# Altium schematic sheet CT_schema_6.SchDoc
size 278 x 170 mm
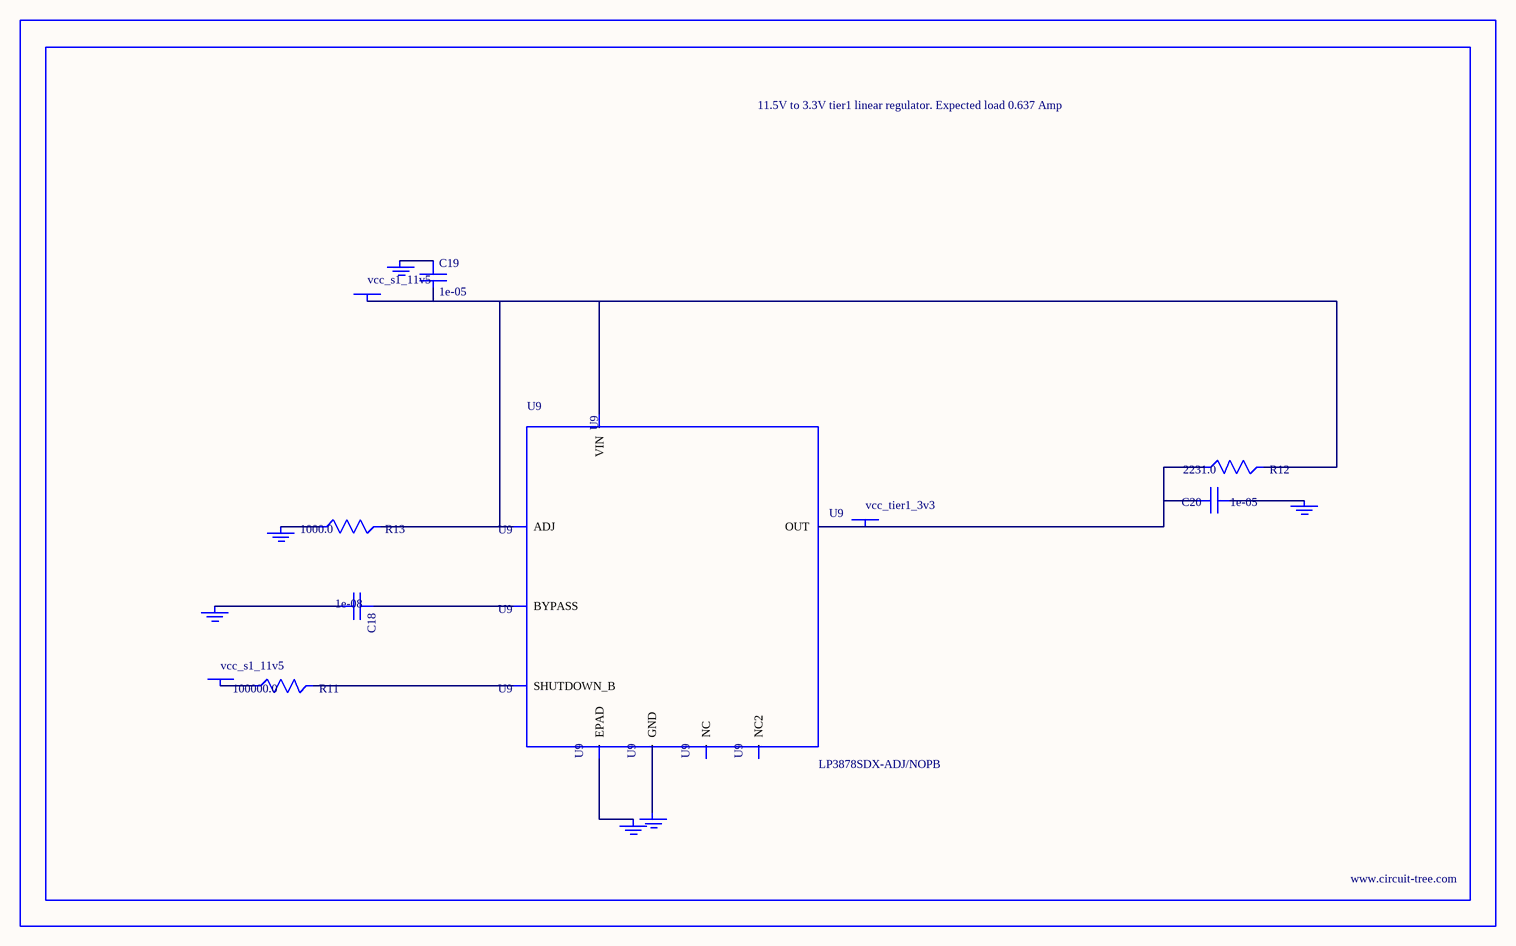
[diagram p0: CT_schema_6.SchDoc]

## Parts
BORDER5  (no value)
C18  1e-08  [C0402]
C19  1e-05  [C1210]
C20  1e-05  [C1210]
GND_INSTANCE_5_0  (no value)
GND_INSTANCE_5_1  (no value)
GND_INSTANCE_5_2  (no value)
GND_INSTANCE_5_3  (no value)
GND_INSTANCE_5_4  (no value)
GND_INSTANCE_5_5  (no value)
POWER_INSTANCE_5_0  vcc_s1_11v5
POWER_INSTANCE_5_1  vcc_s1_11v5
POWER_INSTANCE_5_2  vcc_tier1_3v3
R11  100000.0  [R0603]
R12  2231.0  [R0603]
R13  1000.0  [R0603]
U9  LP3878SDX-ADJ/NOPB  [WSON-8]

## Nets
NetC18_1: C18.1 U9.1(BYPASS)
NetC18_2: C18.2 GND_INSTANCE_5_0.0(GND)
NetC19_1: C19.1 GND_INSTANCE_5_1.0(GND)
NetC19_2: C19.2 POWER_INSTANCE_5_0.0(PWR) R12.2 R13.2 U9.4(VIN) U9.6(ADJ)
NetC20_1: C20.1 GND_INSTANCE_5_2.0(GND)
NetC20_2: C20.2 POWER_INSTANCE_5_2.0(PWR) R12.1 U9.5(OUT)
NetGND_INSTANCE_5_3_0: GND_INSTANCE_5_3.0(GND) R13.1
NetGND_INSTANCE_5_4_0: GND_INSTANCE_5_4.0(GND) U9.PAD(EPAD)
NetGND_INSTANCE_5_5_0: GND_INSTANCE_5_5.0(GND) U9.3(GND)
NetPOWER_INSTANCE_5_1_0: POWER_INSTANCE_5_1.0(PWR) R11.1
NetR11_2: R11.2 U9.8(SHUTDOWN_B)

Not connected (* = marked no-connect by the designer): U9 2(NC) 7(NC2)

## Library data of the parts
BORDER5 = BORDER_PAGE5
C18 = C0402C103K3RAC
C19 = C1210C106K5PACTU
C20 = GRM32DR61E106MA12L
GND_INSTANCE_5_0-GND_INSTANCE_5_5 = GND
POWER_INSTANCE_5_0-POWER_INSTANCE_5_2 = PWR
R11 = RC0603JR-07100KL
R12 = R12
R13 = RC0603JR-071KL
